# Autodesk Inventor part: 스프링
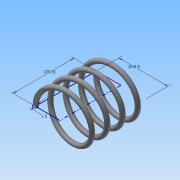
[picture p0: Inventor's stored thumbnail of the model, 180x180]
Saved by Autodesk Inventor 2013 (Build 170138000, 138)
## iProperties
Created: 2015-08
Part Number: 스프링
Material: 일반
Document SubType Name: Modeling
Designer: Administrator
Density: 1 g/cm^3
Author: Administrator
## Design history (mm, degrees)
sketch "스케치1"
  geometry: L1 (0, 0)-(-8.25, 0); L2 (-8.25, 0)-(-8.25, 28); L3 (-8.25, 28)-(0, 28); L4 (0, 28)-(0, 0); C1 r 0.75 at (-8.25, 0)
  constraints: 8 end point, 2 parallel, 1 centre point, 1 coincident, 1 horizontal, 1 perpendicular
  dimensions: "d5" = 16.5 diameter of L2 L4; "d7" = 28 distance of L1.end L2.end (derived); "d8" = 1.5 diameter of C1
feature "코일1" sketch "스케치1" pitch "d9" = 10; turns "d11" = 4; dims "d10" = 28 (= d7), "d12" = 0, angle "d13" = 90 deg, angle "d14" = 90 deg, "d15" = 0, "d16" = 0
sketch "스케치2"
  geometry: L1 (0, -12.5)-(28, -12.5); L2 (28, -12.5)-(28, 12.5); L3 (28, 12.5)-(0, 12.5); L4 (0, 12.5)-(0, -12.5); 4 further points
  constraints: 8 end point, 2 coincident, 2 midpoint, 2 parallel, 1 horizontal, 1 perpendicular
  dimensions: "d17" = 25 distance of L1.end L2.end
extrude "돌출1" sketch "스케치2" stored distance "d19" = 0; taper "d20" = 0 deg
node "솔리드1"
